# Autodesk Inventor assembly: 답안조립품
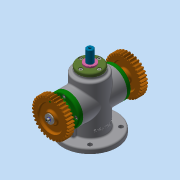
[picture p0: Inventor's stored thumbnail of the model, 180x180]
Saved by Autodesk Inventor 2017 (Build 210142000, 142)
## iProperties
Part Number: 답안조립품
Material: 일반
Document SubType Name: Assembly
Designer: mrc
Mass: 1861.36 g
Surface Area: 1735.36 cm^2
Volume: 520.954 cm^3
Density: 3.57299 g/cm^3
Author: mrc
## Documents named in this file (17)
- C:\Users\mrc\Desktop\600606V1015\답안조립품.iam
- C:\Users\mrc\Desktop\600606V1015\본체.ipt
- C:\Users\mrc\Desktop\600606V1015\가변스프링.ipt
- C:\Users\mrc\Desktop\600606V1015\멈춤링.ipt
- C:\Users\mrc\Desktop\600606V1015\베어링 6203.ipt
- C:\Users\mrc\Desktop\600606V1015\볼트 M4.ipt
- C:\Users\mrc\Desktop\600606V1015\부시.ipt
- C:\Users\mrc\Desktop\600606V1015\스퍼기어.ipt
- C:\Users\mrc\Desktop\600606V1015\스프링와셔.ipt
- C:\Users\mrc\Desktop\600606V1015\스프링조립용 와셔.ipt
- C:\Users\mrc\Desktop\600606V1015\슬라이더.ipt
- C:\Users\mrc\Desktop\600606V1015\오일 실 17 30 8.ipt
- C:\Users\mrc\Desktop\600606V1015\커버 A.ipt
- C:\Users\mrc\Desktop\600606V1015\커버 B.ipt
- C:\Users\mrc\Desktop\600606V1015\키 4x4x12.ipt
- C:\Users\mrc\Desktop\600606V1015\편심축.ipt
- C:\Users\mrc\Desktop\600606V1015\평와셔.ipt
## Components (1 placed, 1 different names)
1. 가변스프링:1
